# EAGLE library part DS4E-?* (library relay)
DS-RELAYS HIGHLY SENSITIVE 1500 V FCC SURGE NAiS WITHSTANDING MINIATURE RELAY Source: http://www.mew-europe.com/.. en_ds_61005_0001.pdf
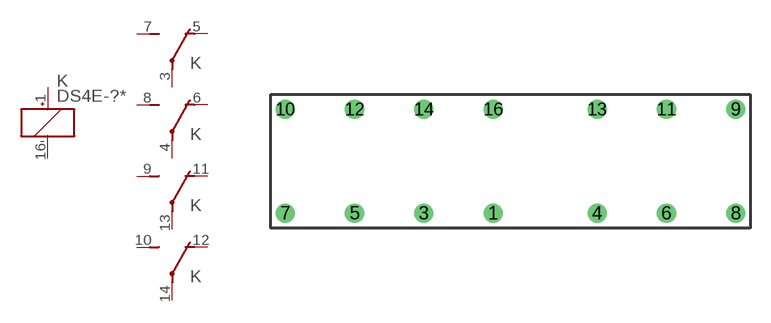
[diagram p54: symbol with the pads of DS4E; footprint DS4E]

Designator prefix K; gates 1=K+- 2=U 3=U 4=U 5=U

## DS4E-1.5V (OC_FARNELL: unknown; OC_NEWARK: unknown), DS4E-3V (OC_FARNELL: unknown; OC_NEWARK: unknown), DS4E-5V (OC_FARNELL: unknown; OC_NEWARK: unknown), DS4E-6V (OC_FARNELL: unknown; OC_NEWARK: unknown), DS4E-9V (OC_FARNELL: unknown; OC_NEWARK: unknown), DS4E-12V (OC_FARNELL: unknown; OC_NEWARK: unknown), DS4E-24V (OC_FARNELL: unknown; OC_NEWARK: unknown), DS4E-48 (OC_FARNELL: unknown; OC_NEWARK: unknown)  [DS4E]
1  1:+  pas
3  2:P  pas
4  3:P  pas
5  2:O  pas
6  3:O  pas
7  2:S  pas
8  3:S  pas
9  4:S  pas
10  5:S  pas
11  4:O  pas
12  5:O  pas
13  4:P  pas
14  5:P  pas
16  1:-  pas

## DS4E-L-1.5V (OC_FARNELL: unknown; OC_NEWARK: unknown), DS4E-L-3V (OC_FARNELL: unknown; OC_NEWARK: unknown), DS4E-L-5V (OC_FARNELL: unknown; OC_NEWARK: unknown), DS4E-L-6V (OC_FARNELL: unknown; OC_NEWARK: unknown), DS4E-L-9V (OC_FARNELL: unknown; OC_NEWARK: unknown), DS4E-L-12V (OC_FARNELL: unknown; OC_NEWARK: unknown), DS4E-L-24V (OC_FARNELL: unknown; OC_NEWARK: unknown), DS4E-L-48V (OC_FARNELL: unknown; OC_NEWARK: unknown)  [DS4E]
Pads as for DS4E

## Footprint DS4E (pad centres in mm)
DS-RELAYS HIGHLY SENSITIVE 1500 V FCC SURGE WITHSTANDING MINIATURE RELAY Source: http://www.mew-europe.com/.. en_ds_61005_0001.pdf
drill 0.9 round: 1 -1.27,-3.81; 3 -6.35,-3.81; 4 6.35,-3.81; 5 -11.43,-3.81; 6 11.43,-3.81; 7 -16.51,-3.81; 8 16.51,-3.81; 9 16.51,3.81; 10 -16.51,3.81; 11 11.43,3.81; 12 -11.43,3.81; 13 6.35,3.81; 14 -6.35,3.81; 16 -1.27,3.81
